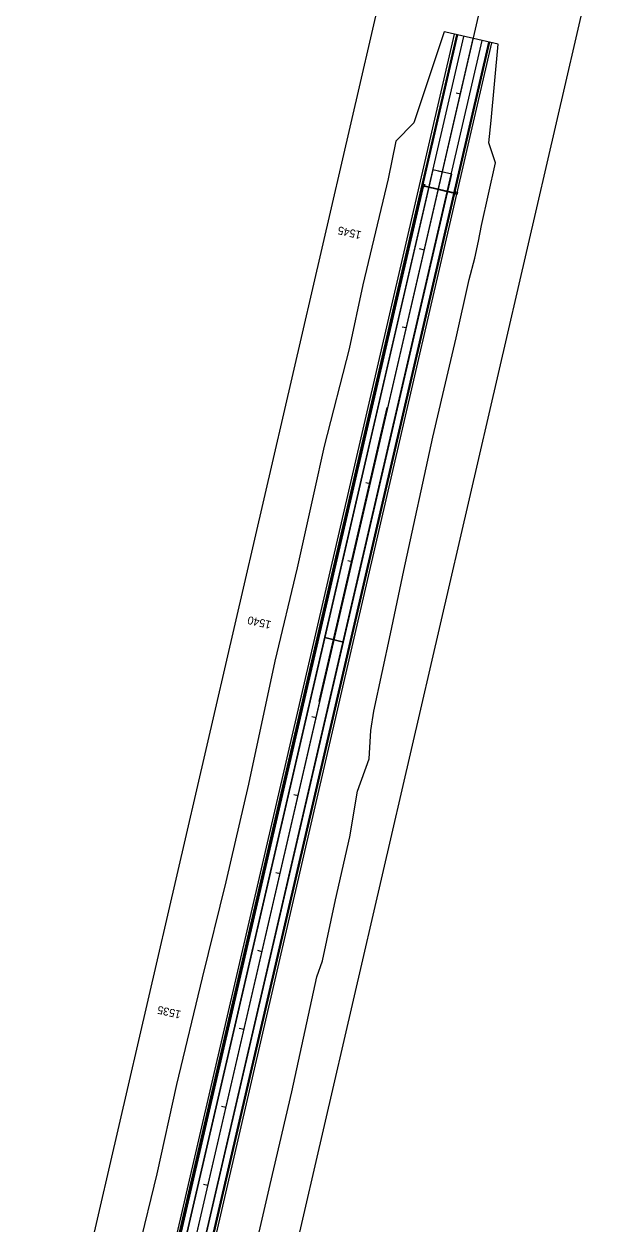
# Model space of a CAD drawing. Extents: x 21596487 to 21601936, y 8263704 to 8275922.
# Drawn here: x 21597973 to 21598711, y 8273528 to 8275027 of the extents above; entities that cross this region are included whole.
import ezdxf

# ---------------------------------------------------------------- set-up
doc = ezdxf.new("R2010")
doc.units = 0
for name, color, linetype in [('Default', 7, 'Continuous'), ('dsnGroundLineIntercept', 7, 'Continuous'), ('dsnPaintPlaceBrokenCenterLineYellow', 7, 'Continuous'), ('dsnPaintPlaceDottedLineYellow', 7, 'Continuous'), ('dsnPaintPlaceDoubleCenterLineYellow', 7, 'Continuous'), ('dsnPaintPlaceEdgeLineLeftYellow', 7, 'Continuous'), ('dsnXsROWLabelLineExist', 7, 'Continuous'), ('EdgePaved', 7, 'Continuous'), ('EdgeUnpaved', 7, 'Continuous'), ('ErosionControl', 7, 'Continuous'), ('Joints', 7, 'Continuous'), ('TC_DNC', 7, 'Continuous'), ('TC_GranularBackFill', 7, 'Continuous'), ('TC_MacadamStone', 7, 'Continuous'), ('TC_SpecialBackfill', 7, 'Continuous'), ('Wall', 7, 'Continuous')]:
    doc.layers.add(name, color=color, linetype=linetype)

msp = doc.modelspace()

# ---------------------------------------------------------------- linework, layer by layer
at = {"layer": 'Default'}
msp.add_line((21596728.7, 8267202.6), (21598588.8, 8275242.6), dxfattribs=at)
msp.add_line((21596728.7, 8267202.6), (21598588.8, 8275242.6), dxfattribs=at)
at = {"layer": 'dsnGroundLineIntercept'}
msp.add_lwpolyline([(21598254.9, 8273463), (21598281, 8273577.1), (21598285.5, 8273596.6), (21598307.9, 8273692.9), (21598339.3, 8273836.3), (21598346.2, 8273856.5), (21598362.4, 8273932.5), (21598380.5, 8274011.3), (21598389.9, 8274068.4), (21598404.6, 8274108.9), (21598406.7, 8274144.4), (21598410.5, 8274168.5), (21598431.2, 8274265.2), (21598448.1, 8274344.4), (21598484.1, 8274511.1), (21598498.3, 8274571.2), (21598513.3, 8274635.2), (21598529.8, 8274708.1), (21598536.6, 8274734.5), (21598541.3, 8274756.1), (21598545.1, 8274775.3), (21598562.5, 8274854), (21598554.2, 8274879), (21598556.9, 8274906.5), (21598565.7, 8275002), (21598565.7, 8275002), (21598565.7, 8275002), (21598565.7, 8275002), (21598500.6, 8275017), (21598500.6, 8275017), (21598500.6, 8275017), (21598500.6, 8275017), (21598498.4, 8275017.6), (21598460.4, 8274903.8), (21598438, 8274881), (21598428.3, 8274833.7), (21598396.8, 8274701.4), (21598379.6, 8274621.4), (21598348.6, 8274499.9), (21598335.7, 8274441.3), (21598314.7, 8274347.7), (21598286.6, 8274231.1), (21598253.8, 8274077.1), (21598225.4, 8273955.4), (21598195.8, 8273835.4), (21598164, 8273702), (21598139.5, 8273590.4), (21598116.6, 8273496.3)], dxfattribs=at)
at = {"layer": 'dsnPaintPlaceBrokenCenterLineYellow'}
for p, q in [((21598342.1, 8274180.7), (21598427, 8274548)), ((21597006.2, 8268402), (21598343, 8274180.5))]:
    msp.add_line(p, q, dxfattribs=at)
at = {"layer": 'dsnPaintPlaceDottedLineYellow'}
for p, q in [((21596717, 8267205.3), (21598523, 8275011.8)), ((21596739.7, 8267200), (21598545.7, 8275006.6))]:
    msp.add_line(p, q, dxfattribs=at)
at = {"layer": 'dsnPaintPlaceDoubleCenterLineYellow'}
msp.add_line((21598428, 8274547.7), (21598534.7, 8275009.1), dxfattribs=at)
at = {"layer": 'dsnPaintPlaceEdgeLineLeftYellow'}
msp.add_line((21598343.1, 8274180.5), (21598428.1, 8274547.7), dxfattribs=at)
at = {"layer": 'dsnXsROWLabelLineExist'}
for p, q in [((21597999.4, 8273249.7), (21598467, 8275270.8)), ((21596850.5, 8267174.4), (21598710.5, 8275214.5))]:
    msp.add_line(p, q, dxfattribs=at)
at = {"layer": 'EdgePaved'}
for points in [[(21598474.1, 8274826.6), (21598473.5, 8274823.7), (21598471.5, 8274824.1), (21598472.2, 8274827.1)], [(21598514.9, 8274817.2), (21598514.2, 8274814.3), (21598512.2, 8274814.7), (21598512.9, 8274817.6)]]:
    msp.add_lwpolyline(points, close=True, dxfattribs=at)
at = {"layer": 'EdgeUnpaved'}
for p, q in [((21596709.9, 8267206.9), (21598472.3, 8274824.9)), ((21596710.4, 8267206.8), (21598472.9, 8274825.4)), ((21598472.3, 8274824.9), (21598512.4, 8274815.6)), ((21598472.4, 8274825.5), (21598512.6, 8274816.2))]:
    msp.add_line(p, q, dxfattribs=at)
at = {"layer": 'ErosionControl'}
for p, q in [((21598518.7, 8274939.6), (21598513.3, 8274940.9)), ((21598496.1, 8274842.2), (21598490.8, 8274843.4)), ((21598473.6, 8274744.8), (21598467.6, 8274746.2)), ((21598451, 8274647.4), (21598445.7, 8274648.6)), ((21598406, 8274452.5), (21598400.6, 8274453.7)), ((21598383.4, 8274355.1), (21598378.1, 8274356.3)), ((21598360.9, 8274257.6), (21598354.9, 8274259)), ((21598338.3, 8274160.2), (21598333, 8274161.5)), ((21598315.8, 8274062.8), (21598310.4, 8274064)), ((21598293.3, 8273965.4), (21598287.9, 8273966.6)), ((21598270.7, 8273867.9), (21598265.4, 8273869.2)), ((21598248.2, 8273770.5), (21598242.2, 8273771.9)), ((21598225.6, 8273673.1), (21598220.3, 8273674.3)), ((21598203.1, 8273575.7), (21598197.8, 8273576.9))]:
    msp.add_line(p, q, dxfattribs=at)
at = {"layer": 'TC_DNC'}
for p, q in [((21596708, 8267207.3), (21598514, 8275013.9)), ((21596749.4, 8267197.8), (21598555.4, 8275004.4))]:
    msp.add_line(p, q, dxfattribs=at)
at = {"layer": 'TC_GranularBackFill'}
msp.add_line((21596728.7, 8267202.6), (21598588.8, 8275242.6), dxfattribs=at)
at = {"layer": 'TC_MacadamStone'}
for p, q in [((21596709.2, 8267207.1), (21598515.3, 8275013.6)), ((21596748.2, 8267198.1), (21598554.2, 8275004.6))]:
    msp.add_line(p, q, dxfattribs=at)
at = {"layer": 'TC_SpecialBackfill'}
for p, q in [((21598484.4, 8274844.9), (21598349.2, 8274260.4)), ((21598507.8, 8274839.5), (21598484.4, 8274844.9)), ((21598372.6, 8274254.9), (21598507.8, 8274839.5)), ((21598349.2, 8274260.4), (21598011.1, 8272799)), ((21598372.6, 8274254.9), (21598349.2, 8274260.4)), ((21598349.2, 8274260.4), (21598372.6, 8274254.9)), ((21598034.5, 8272793.5), (21598372.6, 8274254.9))]:
    msp.add_line(p, q, dxfattribs=at)
at = {"layer": 'Wall'}
for p, q in [((21596705.3, 8267208), (21598511.4, 8275014.5)), ((21596752.1, 8267197.2), (21598558.1, 8275003.7))]:
    msp.add_line(p, q, dxfattribs=at)

# ---------------------------------------------------------------- texts
at = {"layer": 'Joints'}
for s, p in [('1545', (21598395.7, 8274767.9)), ('1540', (21598283, 8274280.8)), ('1535', (21598170.3, 8273793.7))]:
    msp.add_text(s, height=10, rotation=166.974, dxfattribs=at).set_placement(p)

doc.saveas('drawing.dxf')
